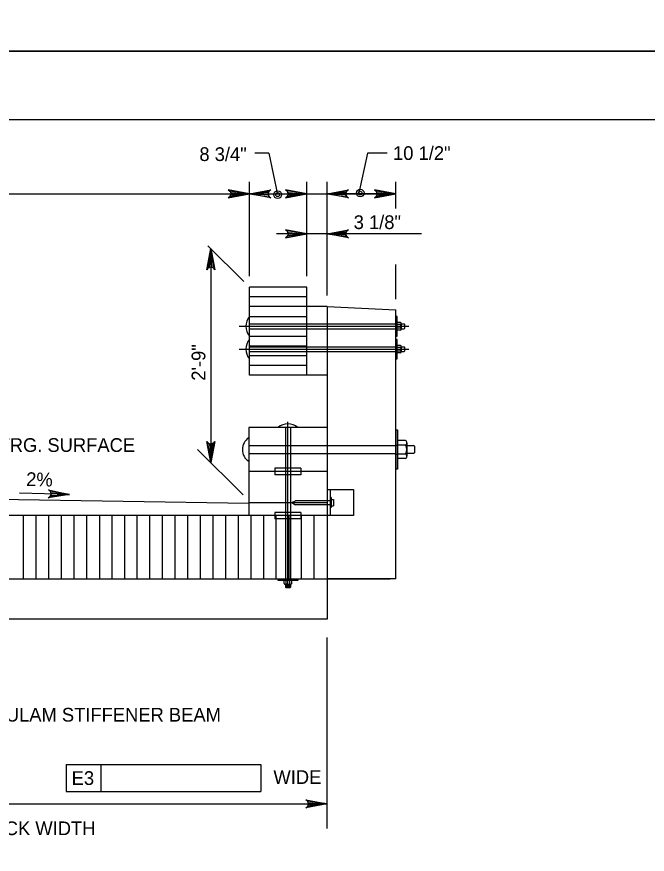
# Model space of a CAD drawing. Extents: x 638268 to 640277, y 295465 to 298435.
# Drawn here: x 638656.9 to 638794.8, y 296477.7 to 296661 of the extents above; entities that cross this region are included whole.
import ezdxf

# ---------------------------------------------------------------- set-up
doc = ezdxf.new("R2010")
doc.units = 0
for name, color, linetype in [('2', 7, 'Continuous'), ('3', 7, 'Continuous'), ('4', 7, 'Continuous'), ('7', 7, 'Continuous'), ('PLT-BNDY', 7, 'Continuous')]:
    doc.layers.add(name, color=color, linetype=linetype)

msp = doc.modelspace()

# ---------------------------------------------------------------- linework, layer by layer
at = {"layer": '2'}
for p, q in [((638475.46, 296638.46), (639261.46, 296638.46)), ((638720.35, 296601.79), (638707.85, 296601.79)), ((638707.85, 296582.51), (638707.85, 296601.79)), ((638720.35, 296582.51), (638720.35, 296601.79)), ((638720.35, 296599.66), (638707.85, 296599.66)), ((638720.35, 296597.52), (638707.85, 296597.52)), ((638724.8, 296597.52), (638720.35, 296597.52)), ((638724.8, 296597.52), (638739.81, 296596.82)), ((638724.8, 296597.52), (638724.8, 296571.1)), ((638739.81, 296537.97), (638739.81, 296596.82)), ((638707.85, 296595.37), (638720.35, 296595.37)), ((638740.14, 296595.37), (638739.81, 296595.37)), ((638740.14, 296591.09), (638740.14, 296595.37)), ((638707.85, 296593.77), (638739.81, 296593.77)), ((638740.14, 296592.39), (638740.14, 296594.05)), ((638740.86, 296594.05), (638740.14, 296594.05)), ((638740.86, 296593.63), (638740.14, 296593.63)), ((638741, 296593.84), (638741, 296592.6)), ((638741, 296593.84), (638741, 296592.6)), ((638741, 296593.75), (638741.64, 296593.75)), ((638741.73, 296593.67), (638741.64, 296593.75)), ((638741.73, 296593.67), (638741.73, 296592.77)), ((638707.85, 296592.7), (638739.81, 296592.7)), ((638707.85, 296591.09), (638720.35, 296591.09)), ((638739.81, 296591.09), (638739.81, 296591.09)), ((638739.81, 296591.09), (638740.14, 296591.09)), ((638740.86, 296592.81), (638740.14, 296592.81)), ((638740.86, 296592.39), (638740.14, 296592.39)), ((638740.14, 296591.09), (638740.14, 296591.09)), ((638741, 296592.67), (638741.64, 296592.67)), ((638741.73, 296592.77), (638741.64, 296592.67)), ((638740.14, 296590.36), (638739.81, 296590.36)), ((638740.14, 296586.08), (638740.14, 296590.36)), ((638707.85, 296588.95), (638720.35, 296588.95)), ((638707.85, 296588.76), (638739.81, 296588.76)), ((638707.85, 296587.7), (638739.81, 296587.7)), ((638740.14, 296587.39), (638740.14, 296589.04)), ((638740.86, 296589.04), (638740.14, 296589.04)), ((638740.86, 296588.62), (638740.14, 296588.62)), ((638740.86, 296587.8), (638740.14, 296587.8)), ((638740.86, 296587.39), (638740.14, 296587.39)), ((638741, 296588.83), (638741, 296587.59)), ((638741, 296588.83), (638741, 296587.59)), ((638741, 296588.76), (638741.64, 296588.76)), ((638741, 296587.7), (638741.64, 296587.7)), ((638741.73, 296588.68), (638741.64, 296588.76)), ((638741.73, 296587.78), (638741.64, 296587.7)), ((638741.73, 296588.68), (638741.73, 296587.78)), ((638707.85, 296586.8), (638720.35, 296586.8)), ((638739.81, 296586.08), (638739.81, 296586.08)), ((638739.81, 296586.08), (638740.14, 296586.08)), ((638740.14, 296586.08), (638740.14, 296586.08)), ((638720.35, 296584.65), (638707.85, 296584.65)), ((638724.8, 296582.51), (638707.85, 296582.51)), ((638724.8, 296571.1), (638707.66, 296571.1)), ((638707.66, 296571.1), (638707.66, 296561.44)), ((638715.71, 296571.1), (638715.71, 296537.97)), ((638716.23, 296536.14), (638716.23, 296572.34)), ((638716.78, 296571.1), (638716.78, 296537.97)), ((638724.8, 296571.1), (638724.8, 296561.44)), ((638739.81, 296570.55), (638739.81, 296561.98)), ((638739.81, 296570.55), (638740.18, 296570.55)), ((638740.18, 296570.55), (638740.18, 296561.98)), ((638739.81, 296567.25), (638740.18, 296567.25)), ((638740.18, 296568.24), (638740.18, 296564.27)), ((638741.93, 296568.24), (638740.18, 296568.24)), ((638741.95, 296567.25), (638740.18, 296567.25)), ((638742.28, 296564.78), (638742.28, 296567.74)), ((638707.66, 296567.14), (638739.81, 296567.14)), ((638742.28, 296567.14), (638742.28, 296567.14)), ((638742.28, 296567.14), (638743.7, 296567.14)), ((638743.88, 296566.99), (638743.7, 296567.14)), ((638743.88, 296565.54), (638743.7, 296565.37)), ((638743.88, 296566.99), (638743.88, 296565.54)), ((638707.66, 296565.37), (638739.81, 296565.37)), ((638739.81, 296565.28), (638740.18, 296565.28)), ((638741.95, 296565.28), (638740.18, 296565.28)), ((638741.91, 296564.27), (638740.18, 296564.27)), ((638743.7, 296565.37), (638742.28, 296565.37)), ((638713.39, 296562.15), (638713.39, 296560.7)), ((638719.09, 296562.15), (638713.39, 296562.15)), ((638719.09, 296562.15), (638719.09, 296560.7)), ((638740.18, 296561.98), (638739.81, 296561.98)), ((638707.66, 296561.44), (638707.66, 296551.79)), ((638724.8, 296561.44), (638707.66, 296561.44)), ((638719.09, 296560.7), (638713.39, 296560.7)), ((638724.8, 296561.44), (638724.8, 296551.79)), ((638668.51, 296556.41), (638657.51, 296556.72)), ((638724.8, 296557.52), (638730.54, 296557.52)), ((638725.48, 296557.52), (638725.48, 296551.79)), ((638730.54, 296557.52), (638730.54, 296551.79)), ((638707.66, 296554.7), (638724.8, 296554.7)), ((638717.1, 296554.64), (638717.87, 296555.07)), ((638717.1, 296554.64), (638717.87, 296554.18)), ((638725.48, 296555.07), (638717.87, 296555.07)), ((638725.67, 296555.73), (638725.48, 296555.73)), ((638725.67, 296555.73), (638725.67, 296553.56)), ((638725.67, 296555.35), (638726.2, 296555.35)), ((638726.2, 296555.35), (638726.2, 296553.94)), ((638725.48, 296554.18), (638717.87, 296554.18)), ((638725.67, 296553.56), (638725.48, 296553.56)), ((638725.67, 296553.94), (638726.2, 296553.94)), ((638713.39, 296552.51), (638713.39, 296551.08)), ((638719.09, 296552.51), (638713.39, 296552.51)), ((638719.09, 296551.08), (638713.39, 296551.08)), ((638719.09, 296552.51), (638719.09, 296551.08)), ((638730.54, 296551.79), (638724.8, 296551.79)), ((638714.1, 296537.61), (638714.1, 296537.97)), ((638715.61, 296537.97), (638715.61, 296537.61)), ((638716.89, 296537.97), (638716.89, 296537.61)), ((638718.4, 296537.97), (638718.4, 296537.97)), ((638718.4, 296537.97), (638718.4, 296537.61)), ((638718.4, 296537.61), (638714.1, 296537.61)), ((638715.41, 296536.92), (638715.41, 296537.61)), ((638715.61, 296536.79), (638716.85, 296536.79)), ((638715.71, 296536.79), (638715.71, 296536.15)), ((638715.8, 296536.06), (638715.71, 296536.15)), ((638716.7, 296536.7), (638715.8, 296536.7)), ((638716.7, 296536.61), (638715.8, 296536.61)), ((638716.7, 296536.51), (638715.8, 296536.51)), ((638716.7, 296536.42), (638715.8, 296536.42)), ((638716.7, 296536.34), (638715.8, 296536.34)), ((638716.7, 296536.23), (638715.8, 296536.23)), ((638716.7, 296536.15), (638715.8, 296536.15)), ((638715.8, 296536.06), (638716.7, 296536.06)), ((638715.82, 296536.92), (638715.82, 296537.61)), ((638716.64, 296536.92), (638716.64, 296537.61)), ((638716.7, 296536.06), (638716.78, 296536.15)), ((638716.78, 296536.79), (638716.78, 296536.15)), ((638717.06, 296536.92), (638717.06, 296537.61)), ((638718.4, 296537.66), (638718.4, 296537.66))]:
    msp.add_line(p, q, dxfattribs=at)
for centre, radius, start, end in [((638710.25, 296593.22), 3.23, 138.5212, 221.4788), ((638740.77, 296593.84), 0.228, 295.2914, 65.298), ((638740.29, 296593.22), 0.703, 323.9035, 35.4998), ((638740.77, 296592.6), 0.227, 294.7299, 65.8765), ((638710.25, 296588.22), 3.23, 138.5212, 221.4788), ((638740.77, 296588.84), 0.228, 295.2914, 65.298), ((638740.29, 296588.22), 0.703, 323.9035, 35.4998), ((638740.77, 296587.6), 0.227, 294.7299, 65.8765), ((638716.23, 296568.65), 3.23, 48.5212, 131.4788), ((638709.34, 296566.25), 3.07, 123.281, 236.7201), ((638741.71, 296567.74), 0.545, 294.1303, 66.5922), ((638740.57, 296566.25), 1.69, 324.4913, 36.1094), ((638741.71, 296564.77), 0.548, 290.9772, 64.7169), ((638715.61, 296537.01), 0.228, 204.702, 334.7086), ((638716.23, 296537.49), 0.703, 234.5002, 306.0965), ((638716.85, 296537.01), 0.227, 204.1235, 335.2701)]:
    msp.add_arc(centre, radius, start, end, dxfattribs=at)
at = {"layer": '3'}
for p, q in [((638724.8, 296597.52), (638724.8, 296544.72)), ((638705.59, 296593.22), (638742.69, 296593.22)), ((638705.59, 296588.25), (638742.69, 296588.25)), ((638625.28, 296555.82), (638707.66, 296554.56)), ((638724.8, 296551.79), (638525.77, 296551.79)), ((638724.8, 296551.79), (638724.8, 296537.97)), ((638525.77, 296537.97), (638724.8, 296537.97)), ((638724.8, 296537.97), (638724.8, 296529.11)), ((638724.8, 296537.97), (638738.62, 296537.97)), ((638739.81, 296537.97), (638724.8, 296537.97)), ((638724.8, 296529.11), (638525.77, 296529.11))]:
    msp.add_line(p, q, dxfattribs=at)
at = {"layer": '4'}
for p, q in [((638712.06, 296631.12), (638709.03, 296631.12)), ((638712.06, 296631.12), (638713.99, 296622.03)), ((638733.63, 296631.12), (638731.7, 296622.03)), ((638737.9, 296631.12), (638733.63, 296631.12)), ((638707.85, 296604.21), (638707.85, 296624.85)), ((638720.35, 296604.21), (638720.35, 296624.85)), ((638724.8, 296599.93), (638724.8, 296624.85)), ((638739.81, 296619), (638739.81, 296624.85)), ((638530.22, 296622.2), (638738.62, 296622.2)), ((638739.81, 296622.2), (638724.8, 296622.2)), ((638745.46, 296613.46), (638713.75, 296613.46)), ((638706.6, 296603.02), (638698.76, 296610.86)), ((638699.38, 296610.24), (638699.38, 296563.39)), ((638739.81, 296599.19), (638739.81, 296606.73)), ((638706.45, 296556.32), (638696.49, 296566.28)), ((638724.8, 296483.35), (638724.8, 296525.1)), ((638667.77, 296497.32), (638710.29, 296497.32)), ((638667.77, 296497.32), (638667.77, 296491.41)), ((638675.33, 296497.32), (638675.33, 296491.41)), ((638710.29, 296497.32), (638710.29, 296491.41)), ((638667.77, 296491.41), (638710.29, 296491.41)), ((638525.77, 296488.73), (638724.8, 296488.73))]:
    msp.add_line(p, q, dxfattribs=at)
for points in [[(638707.85, 296622.2), (638703.19, 296623.07), (638703.55, 296622.82), (638703.73, 296622.51), (638703.79, 296622.2), (638703.73, 296621.89), (638703.55, 296621.57), (638703.19, 296621.32), (638707.85, 296622.2), (638703.55, 296621.57), (638703.73, 296621.89), (638707.85, 296622.2), (638703.79, 296622.2), (638703.73, 296622.51), (638707.85, 296622.2), (638703.55, 296622.82)], [(638707.85, 296622.2), (638712.51, 296623.07), (638712.15, 296622.82), (638711.97, 296622.51), (638711.91, 296622.2), (638711.97, 296621.89), (638712.15, 296621.57), (638712.51, 296621.32), (638707.85, 296622.2), (638712.15, 296621.57), (638711.97, 296621.89), (638707.85, 296622.2), (638711.91, 296622.2), (638711.97, 296622.51), (638707.85, 296622.2), (638712.15, 296622.82)], [(638720.35, 296622.2), (638715.69, 296623.08), (638716.04, 296622.83), (638716.23, 296622.52), (638716.28, 296622.2), (638716.23, 296621.89), (638716.04, 296621.58), (638715.69, 296621.33), (638720.35, 296622.2), (638716.04, 296621.58), (638716.23, 296621.89), (638720.35, 296622.2), (638716.28, 296622.2), (638716.23, 296622.52), (638720.35, 296622.2), (638716.04, 296622.83)], [(638724.8, 296622.2), (638729.46, 296623.08), (638729.11, 296622.83), (638728.92, 296622.52), (638728.87, 296622.2), (638728.92, 296621.89), (638729.11, 296621.58), (638729.46, 296621.33), (638724.8, 296622.2), (638729.11, 296621.58), (638728.92, 296621.89), (638724.8, 296622.2), (638728.87, 296622.2), (638728.92, 296622.52), (638724.8, 296622.2), (638729.11, 296622.83)], [(638739.82, 296622.2), (638735.15, 296623.07), (638735.51, 296622.82), (638735.7, 296622.51), (638735.75, 296622.2), (638735.7, 296621.89), (638735.51, 296621.57), (638735.15, 296621.32), (638739.82, 296622.2), (638735.51, 296621.57), (638735.7, 296621.89), (638739.82, 296622.2), (638735.75, 296622.2), (638735.7, 296622.51), (638739.82, 296622.2), (638735.51, 296622.82)], [(638720.35, 296613.47), (638715.69, 296614.34), (638716.04, 296614.09), (638716.23, 296613.78), (638716.28, 296613.47), (638716.23, 296613.16), (638716.04, 296612.84), (638715.69, 296612.6), (638720.35, 296613.47), (638716.04, 296612.84), (638716.23, 296613.16), (638720.35, 296613.47), (638716.28, 296613.47), (638716.23, 296613.78), (638720.35, 296613.47), (638716.04, 296614.09)], [(638724.8, 296613.47), (638729.46, 296614.34), (638729.11, 296614.09), (638728.92, 296613.78), (638728.87, 296613.47), (638728.92, 296613.16), (638729.11, 296612.84), (638729.46, 296612.6), (638724.8, 296613.47), (638729.11, 296612.84), (638728.92, 296613.16), (638724.8, 296613.47), (638728.87, 296613.47), (638728.92, 296613.78), (638724.8, 296613.47), (638729.11, 296614.09)], [(638699.38, 296610.24), (638700.26, 296605.58), (638700.01, 296605.93), (638699.7, 296606.12), (638699.38, 296606.17), (638699.07, 296606.12), (638698.76, 296605.93), (638698.51, 296605.58), (638699.38, 296610.24), (638698.76, 296605.93), (638699.07, 296606.12), (638699.38, 296610.24), (638699.38, 296606.17), (638699.7, 296606.12), (638699.38, 296610.24), (638700.01, 296605.93)], [(638699.38, 296563.39), (638698.51, 296568.05), (638698.76, 296567.69), (638699.07, 296567.5), (638699.38, 296567.45), (638699.7, 296567.5), (638700.01, 296567.69), (638700.26, 296568.05), (638699.38, 296563.39), (638700.01, 296567.69), (638699.7, 296567.5), (638699.38, 296563.39), (638699.38, 296567.45), (638699.07, 296567.5), (638699.38, 296563.39), (638698.76, 296567.69)], [(638668.51, 296556.41), (638663.83, 296555.67), (638664.19, 296555.91), (638664.39, 296556.22), (638664.45, 296556.53), (638664.4, 296556.84), (638664.23, 296557.16), (638663.87, 296557.42), (638668.51, 296556.41), (638664.23, 296557.16), (638664.4, 296556.84), (638668.51, 296556.41), (638664.45, 296556.53), (638664.39, 296556.22), (638668.51, 296556.41), (638664.19, 296555.91)], [(638724.8, 296488.73), (638720.14, 296487.86), (638720.5, 296488.1), (638720.69, 296488.42), (638720.74, 296488.73), (638720.69, 296489.04), (638720.5, 296489.35), (638720.14, 296489.6), (638724.8, 296488.73), (638720.5, 296489.35), (638720.69, 296489.04), (638724.8, 296488.73), (638720.74, 296488.73), (638720.69, 296488.42), (638724.8, 296488.73), (638720.5, 296488.1)]]:
    msp.add_lwpolyline(points, dxfattribs=at)
for points in [[(638698.93, 296607.52), (638699.83, 296607.52), (638699.38, 296610.24)], [(638699.83, 296566.11), (638698.93, 296566.11), (638699.38, 296563.39)]]:
    msp.add_lwpolyline(points, close=True, dxfattribs=at)
for centre, radius in [((638713.99, 296622.03), 0.833), ((638713.99, 296622.03), 0.417), ((638732.04, 296622.37), 0.833), ((638732.04, 296622.37), 0.417)]:
    msp.add_circle(centre, radius, dxfattribs=at)
at = {"layer": '7'}
for p, q in [((638658.43, 296537.97), (638658.43, 296551.79)), ((638661.19, 296537.97), (638661.19, 296551.79)), ((638663.95, 296537.97), (638663.95, 296551.79)), ((638666.72, 296537.97), (638666.72, 296551.79)), ((638669.48, 296537.97), (638669.48, 296551.79)), ((638672.25, 296537.97), (638672.25, 296551.79)), ((638675.04, 296551.79), (638675.04, 296537.97)), ((638677.77, 296537.97), (638677.77, 296551.79)), ((638680.54, 296537.97), (638680.54, 296551.79)), ((638683.3, 296537.97), (638683.3, 296551.79)), ((638686.06, 296537.97), (638686.06, 296551.79)), ((638688.83, 296537.97), (638688.83, 296551.79)), ((638691.59, 296537.97), (638691.59, 296551.79)), ((638694.36, 296537.97), (638694.36, 296551.79)), ((638697.12, 296537.97), (638697.12, 296551.79)), ((638699.88, 296537.97), (638699.88, 296551.79)), ((638702.65, 296537.97), (638702.65, 296551.79)), ((638705.41, 296537.97), (638705.41, 296551.79)), ((638708.17, 296537.97), (638708.17, 296551.79)), ((638710.94, 296537.97), (638710.94, 296551.79)), ((638713.7, 296537.97), (638713.7, 296551.79)), ((638716.47, 296537.97), (638716.47, 296551.79)), ((638716.51, 296537.97), (638716.51, 296551.79)), ((638719.23, 296537.97), (638719.23, 296551.79)), ((638721.99, 296537.97), (638721.99, 296551.79))]:
    msp.add_line(p, q, dxfattribs=at)
at = {"layer": 'PLT-BNDY'}
for points in [[(638435.46, 297247.46), (639276.46, 297247.46), (639276.46, 296653.46), (638435.46, 296653.46)], [(638435.46, 296653.46), (639276.46, 296653.46), (639276.46, 296059.46), (638435.46, 296059.46)]]:
    msp.add_lwpolyline(points, close=True, dxfattribs=at)

# ---------------------------------------------------------------- texts
at = {"layer": '4'}
for s, p in [('8 3/4"', (638696.88, 296629.39)), ('10 1/2"', (638739.22, 296629.62)), ('BIT. WRG. SURFACE', (638643.15, 296565.74)), ('GLULAM STIFFENER BEAM', (638649.2, 296506.73)), ('E3', (638668.95, 296492.87)), ('WIDE', (638713.07, 296493.08)), ('OUT TO OUT DECK WIDTH', (638622.9, 296481.88))]:
    msp.add_text(s, height=3, dxfattribs=at).set_placement(p)
for s, rotation, p in [('3 1/8"', 360, (638730.61, 296614.5)), ('2\'-9"', 90, (638698.18, 296581.31)), ('2%', 358.4961, (638658.97, 296558.3))]:
    msp.add_text(s, height=3, rotation=rotation, dxfattribs=at).set_placement(p)

doc.saveas('drawing.dxf')
